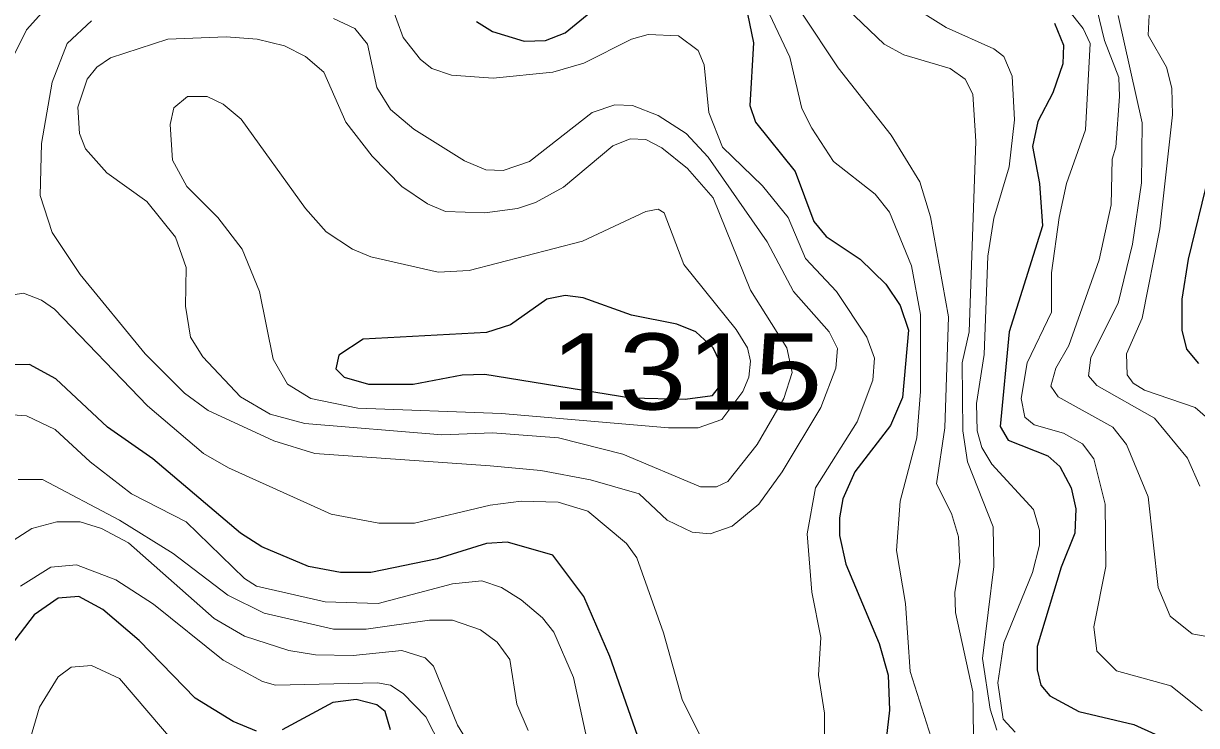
# Model space of a CAD drawing. Extents: x 577 to 602.9, y 7483.8 to 7511.6.
# Drawn here: x 584.69 to 585.923, y 7487.003 to 7487.741 of the extents above; entities that cross this region are included whole.
import ezdxf
from ezdxf.enums import TextEntityAlignment as Align

# ---------------------------------------------------------------- set-up
doc = ezdxf.new("R2010")
doc.units = 0
doc.header["$LTSCALE"] = 0.032
doc.layers.add('1', color=7, linetype='Continuous', lineweight=25)
doc.layers.add('2', color=7, linetype='Continuous', lineweight=13)
doc.layers.add('61', color=7, linetype='Continuous')

msp = doc.modelspace()

# ---------------------------------------------------------------- linework, layer by layer
at = {"layer": '1'}
for points in [[(585.1659, 7487.7429), (585.1826, 7487.7326), (585.216, 7487.7223), (585.2383, 7487.7231), (585.259, 7487.731), (585.3186, 7487.7803)], [(585.4506, 7487.7509), (585.457, 7487.7207), (585.453, 7487.6547), (585.4593, 7487.6372), (585.5007, 7487.5855), (585.5206, 7487.533), (585.5333, 7487.5171), (585.5691, 7487.4932), (585.5961, 7487.467), (585.6112, 7487.4447), (585.62, 7487.4185), (585.6136, 7487.3477), (585.6009, 7487.3183), (585.5635, 7487.2698), (585.5508, 7487.2412), (585.5476, 7487.2213), (585.5476, 7487.203)], [(585.7734, 7487.7413), (585.783, 7487.7183), (585.7822, 7487.6984), (585.7718, 7487.6682), (585.7559, 7487.638), (585.7504, 7487.6117), (585.7575, 7487.5728), (585.7607, 7487.5282), (585.7257, 7487.4169), (585.7162, 7487.3175), (585.7249, 7487.3032), (585.7663, 7487.2865)], [(585.9253, 7487.3835), (585.9126, 7487.3986), (585.9078, 7487.4185), (585.9078, 7487.4511), (585.9142, 7487.4932), (585.9356, 7487.5807)], [(585.3424, 7486.9716), (585.3059, 7487.0758), (585.2788, 7487.1386), (585.2462, 7487.1823), (585.1985, 7487.1958), (585.1763, 7487.1943), (585.1246, 7487.1784), (585.0546, 7487.164), (585.0228, 7487.164), (584.9894, 7487.1704), (584.9401, 7487.1911), (584.9178, 7487.2054), (584.8256, 7487.2833), (584.7779, 7487.3167), (584.7238, 7487.3676), (584.696, 7487.3827), (584.661, 7487.3819)], [(585.7663, 7487.2865), (585.779, 7487.2754), (585.7909, 7487.2531), (585.7957, 7487.2308), (585.7949, 7487.2054), (585.7806, 7487.1696), (585.7551, 7487.0861), (585.7551, 7487.0615), (585.7591, 7487.0456), (585.7687, 7487.0344), (585.7989, 7487.0177), (585.8569, 7487.0042), (585.8792, 7486.9939)], [(585.5476, 7487.203), (585.554, 7487.1728), (585.589, 7487.0893), (585.5985, 7487.0559), (585.6001, 7487.0193), (585.5953, 7486.9796)], [(584.9345, 7486.9971), (584.9099, 7487.0074), (584.8701, 7487.032), (584.8113, 7487.0925), (584.7731, 7487.1251), (584.7477, 7487.1386), (584.7262, 7487.137), (584.7007, 7487.1195), (584.6761, 7487.0869)], [(585.0753, 7486.9986), (585.0697, 7487.0177), (585.061, 7487.0249), (585.0395, 7487.0305), (585.0148, 7487.0273), (584.9616, 7486.9986)]]:
    msp.add_lwpolyline(points, dxfattribs=at)
msp.add_lwpolyline([(585.3281, 7487.3474), (585.3853, 7487.346), (585.414, 7487.3501), (585.4228, 7487.3612), (585.4251, 7487.3779), (585.4148, 7487.4002), (585.3965, 7487.4169), (585.3766, 7487.4249), (585.3289, 7487.4344), (585.278, 7487.4527), (585.259, 7487.4551), (585.2399, 7487.4511), (585.2017, 7487.4241), (585.1763, 7487.4161), (585.0466, 7487.409), (585.0212, 7487.3923), (585.018, 7487.3779), (585.0268, 7487.3692), (585.0522, 7487.362), (585.0991, 7487.362), (585.1508, 7487.3716), (585.1747, 7487.3724)], close=True, dxfattribs=at)
at = {"layer": '2'}
for points in [[(585.5174, 7487.793), (585.5945, 7487.7191), (585.6152, 7487.7079), (585.6637, 7487.6936), (585.6796, 7487.6825), (585.6876, 7487.6666), (585.6907, 7487.6173), (585.6836, 7487.4169), (585.6764, 7487.3843), (585.6772, 7487.3127), (585.682, 7487.2801), (585.709, 7487.2118), (585.7098, 7487.1704), (585.6979, 7487.0734), (585.7058, 7487.0205), (585.7128, 7486.9984)], [(585.9508, 7487.3119), (585.9213, 7487.3374), (585.8681, 7487.3557), (585.8561, 7487.3628), (585.8498, 7487.3716), (585.849, 7487.3938), (585.8657, 7487.4312), (585.884, 7487.5251), (585.8975, 7487.6451), (585.8967, 7487.673), (585.8911, 7487.6952), (585.872, 7487.7286), (585.8752, 7487.7922)], [(585.6462, 7486.9827), (585.6216, 7487.0599), (585.6168, 7487.1314), (585.6072, 7487.1871), (585.6112, 7487.2388), (585.6287, 7487.3056), (585.6327, 7487.3541), (585.6327, 7487.4351), (585.6231, 7487.4861), (585.6001, 7487.5425), (585.585, 7487.5616), (585.5412, 7487.5958), (585.5182, 7487.6308), (585.5078, 7487.6515), (585.4951, 7487.7056), (585.4617, 7487.7771)], [(585.5317, 7486.9748), (585.5317, 7487.0161), (585.5253, 7487.0559), (585.5277, 7487.0957), (585.5182, 7487.1434), (585.5134, 7487.2046), (585.5222, 7487.2531), (585.5659, 7487.3223), (585.5826, 7487.366), (585.5842, 7487.3891), (585.5762, 7487.4113), (585.5444, 7487.4591), (585.5118, 7487.494), (585.4935, 7487.537), (585.4665, 7487.5704), (585.4244, 7487.6109), (585.41, 7487.6475), (585.4053, 7487.6976), (585.3989, 7487.7127), (585.3782, 7487.7278), (585.3464, 7487.7294), (585.3289, 7487.7246), (585.2788, 7487.6992), (585.2462, 7487.6897), (585.1834, 7487.6833), (585.1397, 7487.6865), (585.119, 7487.6936), (585.1071, 7487.7032), (585.0888, 7487.7262), (585.0753, 7487.7628)], [(585.7321, 7486.9963), (585.7194, 7487.0098), (585.7138, 7487.0479), (585.7202, 7487.0901), (585.7504, 7487.164), (585.7575, 7487.1927), (585.7575, 7487.2086), (585.7512, 7487.23), (585.7074, 7487.2778), (585.6971, 7487.2952), (585.6923, 7487.3127), (585.6915, 7487.3414), (585.6995, 7487.3931), (585.7035, 7487.4964), (585.7098, 7487.5362), (585.7257, 7487.5903), (585.7313, 7487.6396), (585.7289, 7487.6857), (585.7202, 7487.7064), (585.7098, 7487.7143), (585.6597, 7487.7366), (585.6192, 7487.762)], [(584.7119, 7487.7557), (584.6928, 7487.7342), (584.6642, 7487.6769), (584.6435, 7487.6626), (584.6204, 7487.6674), (584.587, 7487.6841), (584.5433, 7487.7254), (584.529, 7487.731), (584.5043, 7487.7334), (584.4399, 7487.7167), (584.4002, 7487.7207), (584.3644, 7487.7183), (584.3294, 7487.7087), (584.2785, 7487.6873), (584.1902, 7487.669), (584.1592, 7487.6531), (584.1346, 7487.6531), (584.1211, 7487.6586), (584.1123, 7487.669), (584.1099, 7487.6833), (584.1004, 7487.696), (584.0773, 7487.7095), (584.001, 7487.7215), (583.9739, 7487.7215)], [(585.6883, 7486.9931), (585.6876, 7487.0384), (585.6693, 7487.1219), (585.6685, 7487.1434), (585.674, 7487.1744), (585.6724, 7487.2014), (585.6653, 7487.2261), (585.6494, 7487.2571), (585.6581, 7487.3159), (585.6621, 7487.4328), (585.643, 7487.5378), (585.6319, 7487.5744), (585.6017, 7487.6237), (585.546, 7487.6944), (585.5078, 7487.7517)], [(585.9285, 7487.0185), (585.8959, 7487.0448), (585.8386, 7487.0607), (585.818, 7487.0813), (585.8148, 7487.1068), (585.8275, 7487.1704), (585.8267, 7487.2356), (585.8148, 7487.2833), (585.8029, 7487.2992), (585.783, 7487.3104), (585.752, 7487.3191), (585.7424, 7487.3271), (585.7384, 7487.3469), (585.7448, 7487.3843), (585.7703, 7487.4376), (585.7703, 7487.4789), (585.7782, 7487.537), (585.7862, 7487.5728), (585.806, 7487.6292), (585.8108, 7487.7199), (585.8036, 7487.7358), (585.787, 7487.7564)], [(585.9603, 7487.0917), (585.9182, 7487.0996), (585.8951, 7487.1179), (585.8824, 7487.1481), (585.872, 7487.2436), (585.849, 7487.2984), (585.8347, 7487.3167), (585.7774, 7487.3485), (585.7695, 7487.3597), (585.775, 7487.3787), (585.7885, 7487.4026), (585.8203, 7487.4925), (585.8331, 7487.5505), (585.8339, 7487.5982), (585.8378, 7487.6109), (585.8418, 7487.6642), (585.841, 7487.6841), (585.8259, 7487.7231), (585.818, 7487.7564)], [(585.8402, 7487.7493), (585.8657, 7487.6364), (585.8649, 7487.5736), (585.8553, 7487.5091), (585.8402, 7487.4471), (585.8116, 7487.3899), (585.8092, 7487.3708), (585.818, 7487.3605), (585.8784, 7487.3263), (585.9134, 7487.2841), (585.9261, 7487.2547)], [(585.0156, 7487.7461), (585.0379, 7487.7358), (585.0514, 7487.7191), (585.061, 7487.6738), (585.0753, 7487.6507), (585.0999, 7487.63), (585.1532, 7487.5966), (585.1755, 7487.5871), (585.1937, 7487.5863), (585.2216, 7487.5958), (585.2876, 7487.6475), (585.3114, 7487.6555), (585.3297, 7487.6547), (585.3568, 7487.6443), (585.3862, 7487.6252), (585.4092, 7487.6006), (585.4713, 7487.5115), (585.4991, 7487.4591), (585.5365, 7487.4169), (585.5452, 7487.3994), (585.5436, 7487.3787), (585.5277, 7487.3374), (585.4872, 7487.2698), (585.4625, 7487.2356), (585.4347, 7487.2125), (585.4116, 7487.2046), (585.3925, 7487.2062), (585.3663, 7487.2189), (585.3369, 7487.2467), (585.2856, 7487.2612), (585.2333, 7487.2711), (585.1802, 7487.2762), (584.9958, 7487.2889), (584.9528, 7487.3024), (584.8836, 7487.3342), (584.859, 7487.3525), (584.8176, 7487.3938), (584.7492, 7487.4773), (584.7198, 7487.5211), (584.7071, 7487.56), (584.7087, 7487.6149), (584.7198, 7487.6793), (584.7357, 7487.7199), (584.7612, 7487.7437)], [(584.6546, 7487.4519), (584.6896, 7487.4575), (584.7087, 7487.4503), (584.7222, 7487.4408), (584.82, 7487.339), (584.8789, 7487.2889), (584.9051, 7487.2738), (585.0132, 7487.2253), (585.0633, 7487.2157), (585.1007, 7487.2157), (585.1802, 7487.2348), (585.2128, 7487.2388), (585.2518, 7487.238), (585.2828, 7487.2285), (585.3234, 7487.1943), (585.3345, 7487.1792), (585.3623, 7487.1004), (585.3822, 7487.0305), (585.4037, 7486.9867)], [(584.6578, 7487.331), (584.6928, 7487.3286), (584.723, 7487.3143), (584.7596, 7487.2801), (584.8033, 7487.2467), (584.8606, 7487.2173), (584.9218, 7487.1577), (584.9345, 7487.1497), (585.0069, 7487.133), (585.0625, 7487.1314), (585.1405, 7487.1521), (585.1715, 7487.1553), (585.1922, 7487.1481), (585.2128, 7487.1354), (585.2351, 7487.1163), (585.247, 7487.1012), (585.2677, 7487.0535), (585.2836, 7486.9812)], [(584.684, 7487.2618), (584.7095, 7487.2618), (584.7906, 7487.2189), (584.8471, 7487.1839), (584.9043, 7487.1402), (584.9425, 7487.1211), (585.0156, 7487.1044), (585.0498, 7487.1044), (585.1166, 7487.1139), (585.1405, 7487.1139), (585.1699, 7487.1036), (585.1874, 7487.0909), (585.2009, 7487.0726), (585.2081, 7487.0257), (585.22, 7486.9979)], [(585.158, 7486.9835), (585.146, 7487.0034), (585.1206, 7487.0654), (585.1118, 7487.0742), (585.0872, 7487.0821), (585.0363, 7487.0766), (584.9965, 7487.0774), (584.9687, 7487.0821), (584.9218, 7487.0972), (584.89, 7487.1155), (584.8001, 7487.1951), (584.7715, 7487.2102), (584.7492, 7487.2173), (584.7246, 7487.2173), (584.6984, 7487.2102), (584.6737, 7487.1943)], [(584.6864, 7487.1497), (584.7182, 7487.1696), (584.7453, 7487.172), (584.7866, 7487.1561), (584.8264, 7487.1306), (584.8995, 7487.0718), (584.9409, 7487.0495), (584.9544, 7487.0456), (585.0618, 7487.0479), (585.0753, 7487.0456), (585.0888, 7487.0368), (585.1126, 7487.0122), (585.1452, 7486.9486)], [(584.6801, 7486.9326), (584.7063, 7487.0225), (584.7262, 7487.0543), (584.7397, 7487.0646), (584.7612, 7487.0662), (584.7906, 7487.0527), (584.8502, 7486.9827)]]:
    msp.add_lwpolyline(points, dxfattribs=at)
for points in [[(585.1293, 7487.3088), (584.9854, 7487.3207), (584.9488, 7487.3302), (584.9178, 7487.3485), (584.8781, 7487.3907), (584.8653, 7487.4113), (584.8598, 7487.4439), (584.8606, 7487.4845), (584.8494, 7487.5163), (584.8192, 7487.5537), (584.7771, 7487.5839), (584.7548, 7487.6093), (584.7485, 7487.6252), (584.7469, 7487.6531), (584.7564, 7487.6825), (584.7667, 7487.6952), (584.7811, 7487.7048), (584.8415, 7487.7246), (584.9027, 7487.727), (584.9353, 7487.7246), (584.9639, 7487.7175), (584.9862, 7487.7064), (585.0053, 7487.6897), (585.0284, 7487.6372), (585.0562, 7487.6014), (585.0872, 7487.5696), (585.1142, 7487.5513), (585.1333, 7487.5433), (585.1747, 7487.5418), (585.2089, 7487.5465), (585.2279, 7487.5529), (585.2574, 7487.5688), (585.3091, 7487.6125), (585.3273, 7487.6197), (585.344, 7487.6189), (585.3607, 7487.6101), (585.3878, 7487.5887), (585.4148, 7487.5577), (585.4538, 7487.4606), (585.4919, 7487.4002), (585.4975, 7487.374), (585.4888, 7487.3469), (585.4609, 7487.2984), (585.4299, 7487.2595), (585.418, 7487.2539), (585.4013, 7487.2539), (585.3196, 7487.2884), (585.252, 7487.3056), (585.1825, 7487.3108)], [(585.1922, 7487.331), (585.0411, 7487.3366), (584.9918, 7487.3469), (584.9671, 7487.362), (584.952, 7487.3883), (584.9377, 7487.4591), (584.9194, 7487.5036), (584.894, 7487.537), (584.8614, 7487.5696), (584.8463, 7487.5974), (584.8439, 7487.6348), (584.8478, 7487.6523), (584.8622, 7487.6642), (584.8828, 7487.6642), (584.8995, 7487.6563), (584.9186, 7487.6404), (584.9862, 7487.5465), (585.0077, 7487.5219), (585.0355, 7487.5036), (585.0546, 7487.4956), (585.1254, 7487.4797), (585.158, 7487.4813), (585.2772, 7487.5123), (585.344, 7487.5433), (585.3568, 7487.5457), (585.3631, 7487.5418), (585.3838, 7487.4877), (585.4387, 7487.4193), (585.4506, 7487.4002), (585.4538, 7487.3859), (585.4522, 7487.3692), (585.4458, 7487.3541), (585.4236, 7487.3247), (585.3989, 7487.3159), (585.3675, 7487.3159)]]:
    msp.add_lwpolyline(points, close=True, dxfattribs=at)

# ---------------------------------------------------------------- texts
at = {"layer": '61', "width": 1.2}
msp.add_text('1315', height=0.08, dxfattribs=at).set_placement((585.3866, 7487.3352), align=Align.CENTER)

doc.saveas('drawing.dxf')
